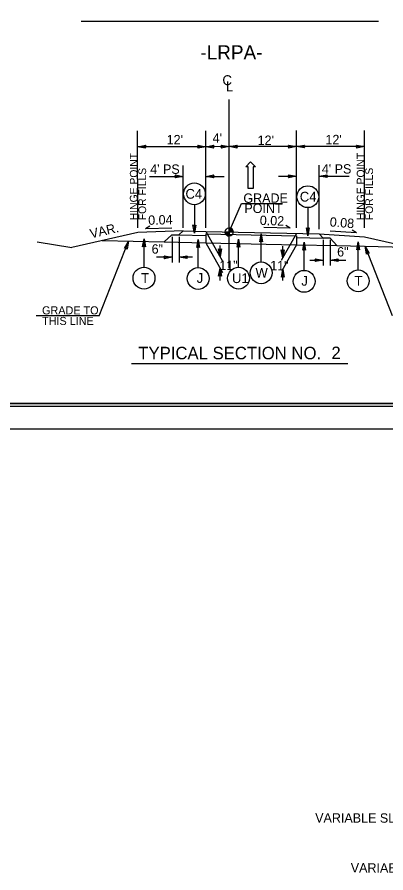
# Model space of a CAD drawing. Extents: x 2241081 to 2251104, y 658534 to 663427.
# Drawn here: x 2243527 to 2243852, y 661352 to 662106 of the extents above; entities that cross this region are included whole.
import ezdxf

# ---------------------------------------------------------------- set-up
doc = ezdxf.new("R2010")
doc.units = 0
for name, color, linetype in [('Old_Level_1', 7, 'Continuous'), ('Old_Level_11', 7, 'Continuous'), ('Old_Level_2', 7, 'Continuous'), ('Old_Level_3', 7, 'Continuous'), ('Prop Dimension Text', 7, 'Continuous'), ('Prop Lane Arrow CELL', 7, 'Continuous'), ('Prop PHM Text', 7, 'Continuous'), ('Sheet Cutting Line CELL', 7, 'Continuous'), ('Sheet Plan CELL', 7, 'Continuous'), ('Sheet Plot Border Inside CELL', 7, 'Continuous'), ('Sheet Plot Border Outside CELL', 7, 'Continuous'), ('Typical Arrow Superelevation CELL', 7, 'Continuous'), ('Typical Berm Information CELL', 7, 'Continuous'), ('Typical Grade Point Symbol CELL', 7, 'Continuous'), ('Typical Hinge Slope Interstate CELL', 7, 'Continuous'), ('Typical ID Circle CELL', 7, 'Continuous'), ('Typical Terminator CELL', 7, 'Continuous'), ('Typical Text Centerline CELL', 7, 'Continuous'), ('Typical Text Grade Point CELL', 7, 'Continuous'), ('Typical Text ID Circle CELL', 7, 'Continuous'), ('Typical Text Label CELL', 7, 'Continuous')]:
    doc.layers.add(name, color=color, linetype=linetype)

msp = doc.modelspace()

# ---------------------------------------------------------------- linework, layer by layer
at = {"layer": 'Old_Level_1'}
for p, q in [((2243633.23, 661915.97), (2243575.21, 661902.69)), ((2243833.22, 661912.13), (2243891.23, 661898.85))]:
    msp.add_line(p, q, dxfattribs=at)
at = {"layer": 'Old_Level_11'}
for p, q in [((2243599.25, 661842.46), (2243625.26, 661908.29)), ((2243857.83, 661842.43), (2243833.58, 661903.83))]:
    msp.add_line(p, q, dxfattribs=at)
at = {"layer": 'Old_Level_2'}
for p, q in [((2243673.22, 661917.27), (2243633.23, 661915.97)), ((2243673.22, 661917.27), (2243669.42, 661913.73)), ((2243673.22, 661917.27), (2243693.22, 661916.84)), ((2243693.22, 661916.84), (2243793.22, 661914.7)), ((2243693.22, 661914.73), (2243693.22, 661906.84)), ((2243693.22, 661914.73), (2243773.22, 661913.02)), ((2243793.22, 661914.7), (2243833.22, 661912.13)), ((2243793.22, 661914.7), (2243796.67, 661911.01)), ((2243544.72, 661907.78), (2243575.21, 661902.69)), ((2243601.87, 661908.79), (2243656.66, 661907.62)), ((2243663.31, 661913.81), (2243656.66, 661907.62)), ((2243656.66, 661907.62), (2243693.22, 661906.84)), ((2243663.31, 661913.81), (2243669.42, 661913.73)), ((2243669.42, 661913.73), (2243693.22, 661913.22)), ((2243773.23, 661913.02), (2243773.23, 661905.12)), ((2243773.23, 661911.51), (2243796.67, 661911.01)), ((2243802.78, 661910.92), (2243796.67, 661911.01)), ((2243802.78, 661910.92), (2243808.89, 661904.36)), ((2243693.22, 661906.84), (2243773.23, 661905.12)), ((2243773.23, 661905.12), (2243808.89, 661904.36)), ((2243808.89, 661904.36), (2243873.16, 661902.98))]:
    msp.add_line(p, q, dxfattribs=at)
at = {"layer": 'Prop Dimension Text'}
for p, q in [((2243633.22, 661919.92), (2243633.17, 662005.51)), ((2243693.22, 661919.96), (2243693.17, 662005.55)), ((2243773.22, 661920.01), (2243773.17, 662005.6)), ((2243833.22, 661920.04), (2243833.17, 662005.63)), ((2243693.18, 661991.48), (2243633.18, 661991.44)), ((2243713.86, 661991.49), (2243693.18, 661991.48)), ((2243753.18, 661991.52), (2243713.86, 661991.49)), ((2243773.18, 661991.53), (2243753.18, 661991.52)), ((2243833.18, 661991.56), (2243773.18, 661991.53)), ((2243673.22, 661919.95), (2243673.19, 661975.03)), ((2243793.22, 661918.71), (2243793.19, 661975.1)), ((2243643.74, 661965.32), (2243673.19, 661965.34)), ((2243693.19, 661965.35), (2243709.57, 661965.36)), ((2243757.46, 661965.39), (2243773.19, 661965.4)), ((2243793.19, 661965.41), (2243819.53, 661965.43)), ((2243693.22, 661916.84), (2243707.98, 661890.66)), ((2243773.24, 661915.12), (2243759.71, 661891.13)), ((2243663.63, 661912.05), (2243663.63, 661889.44)), ((2243669.74, 661912.05), (2243669.74, 661889.44)), ((2243796.67, 661909.55), (2243796.67, 661886.94)), ((2243802.78, 661909.55), (2243802.78, 661886.94)), ((2243693.22, 661906.84), (2243707.97, 661880.66)), ((2243705.78, 661894.57), (2243705.77, 661904.37)), ((2243773.23, 661905.12), (2243760.25, 661882.09)), ((2243761.07, 661893.54), (2243761.07, 661903.93)), ((2243663.57, 661894.06), (2243649.7, 661894.05)), ((2243681.39, 661894.07), (2243669.74, 661894.06)), ((2243705.79, 661873.61), (2243705.79, 661884.56)), ((2243785.01, 661891.57), (2243796.67, 661891.56)), ((2243802.84, 661891.56), (2243816.71, 661891.55)), ((2243761.05, 661873.57), (2243761.06, 661883.53)), ((2243599.25, 661842.46), (2243543.76, 661842.43))]:
    msp.add_line(p, q, dxfattribs=at)
at = {"layer": 'Prop Lane Arrow CELL'}
for p, q in [((2243728.45, 661973.86), (2243732.72, 661978.21)), ((2243732.72, 661978.21), (2243737.14, 661973.87)), ((2243730.52, 661973.86), (2243728.45, 661973.86)), ((2243730.53, 661954.57), (2243730.52, 661973.86)), ((2243737.14, 661973.87), (2243735.07, 661973.87)), ((2243735.07, 661973.87), (2243735.08, 661954.57)), ((2243735.08, 661954.57), (2243730.53, 661954.57))]:
    msp.add_line(p, q, dxfattribs=at)
at = {"layer": 'Sheet Cutting Line CELL'}
msp.add_line((2242806.13, 661742.89), (2244489.63, 661742.89), dxfattribs=at)
at = {"layer": 'Sheet Plan CELL'}
for points in [[(2242972.61, 661765.4), (2242972.59, 662815.38), (2244272.58, 662815.42), (2244272.59, 662665.35), (2244472.63, 662665.34), (2244472.63, 661765.4)], [(2244472.65, 662815.4), (2242972.62, 662815.4), (2242972.61, 661765.4), (2244472.63, 661765.4)]]:
    msp.add_lwpolyline(points, close=True, dxfattribs=at)
at = {"layer": 'Sheet Plot Border Inside CELL'}
msp.add_lwpolyline([(2242819.13, 661762.89), (2244485.11, 661762.9), (2244485.13, 662817.89), (2242819.13, 662817.89)], close=True, dxfattribs=at)
at = {"layer": 'Sheet Plot Border Outside CELL'}
msp.add_lwpolyline([(2242806.13, 661742.89), (2244489.63, 661742.89), (2244489.63, 662837.89), (2242806.13, 662837.89)], close=True, dxfattribs=at)
at = {"layer": 'Typical Arrow Superelevation CELL'}
for p, q in [((2243767.75, 661919.82), (2243763.83, 661922.19)), ((2243640.13, 661919.31), (2243644.02, 661921.71)), ((2243640.13, 661919.31), (2243663.42, 661920.01)), ((2243767.75, 661919.82), (2243744.45, 661920.29)), ((2243826.09, 661915.49), (2243802.83, 661916.95)), ((2243826.09, 661915.49), (2243822.28, 661918.02))]:
    msp.add_line(p, q, dxfattribs=at)
at = {"layer": 'Typical Grade Point Symbol CELL'}
for p, q in [((2243710.33, 661916.4), (2243713.91, 661916.4)), ((2243713.92, 661919.98), (2243713.91, 661916.4)), ((2243713.91, 661916.4), (2243713.92, 661919.98)), ((2243713.91, 661916.4), (2243713.91, 661912.82)), ((2243717.49, 661916.4), (2243713.91, 661916.4))]:
    msp.add_line(p, q, dxfattribs=at)
for points in [[(2243710.37, 661915.89), (2243710.37, 661916.4)], [(2243710.44, 661915.52), (2243710.44, 661916.4)], [(2243710.51, 661915.27), (2243710.51, 661916.4)], [(2243710.58, 661915.08), (2243710.58, 661916.4)], [(2243710.66, 661914.91), (2243710.66, 661916.4)], [(2243710.73, 661914.76), (2243710.73, 661916.4)], [(2243710.8, 661914.63), (2243710.8, 661916.4)], [(2243710.87, 661914.51), (2243710.87, 661916.4)], [(2243710.94, 661914.4), (2243710.94, 661916.4)], [(2243711.01, 661914.3), (2243711.01, 661916.4)], [(2243711.08, 661914.2), (2243711.08, 661916.4)], [(2243711.16, 661914.11), (2243711.16, 661916.4)], [(2243711.23, 661914.03), (2243711.23, 661916.4)], [(2243711.3, 661913.95), (2243711.3, 661916.4)], [(2243711.37, 661913.87), (2243711.37, 661916.4)], [(2243711.44, 661913.8), (2243711.44, 661916.4)], [(2243711.51, 661913.74), (2243711.51, 661916.4)], [(2243711.59, 661913.67), (2243711.59, 661916.4)], [(2243711.66, 661913.61), (2243711.66, 661916.4)], [(2243711.73, 661913.56), (2243711.73, 661916.4)], [(2243711.8, 661913.51), (2243711.8, 661916.4)], [(2243711.87, 661913.45), (2243711.87, 661916.4)], [(2243711.94, 661913.4), (2243711.94, 661916.4)], [(2243712.02, 661913.36), (2243712.02, 661916.4)], [(2243712.09, 661913.32), (2243712.09, 661916.4)], [(2243712.16, 661913.28), (2243712.16, 661916.4)], [(2243712.23, 661913.24), (2243712.23, 661916.4)], [(2243712.3, 661913.2), (2243712.3, 661916.4)], [(2243712.37, 661913.17), (2243712.37, 661916.4)], [(2243712.45, 661913.13), (2243712.45, 661916.4)], [(2243712.52, 661913.1), (2243712.52, 661916.4)], [(2243712.59, 661913.07), (2243712.59, 661916.4)], [(2243712.66, 661913.04), (2243712.66, 661916.4)], [(2243712.73, 661913.01), (2243712.73, 661916.4)], [(2243712.8, 661912.99), (2243712.8, 661916.4)], [(2243712.88, 661912.97), (2243712.88, 661916.4)], [(2243712.95, 661912.95), (2243712.95, 661916.4)], [(2243713.02, 661912.93), (2243713.02, 661916.4)], [(2243713.09, 661912.91), (2243713.09, 661916.4)], [(2243713.16, 661912.9), (2243713.16, 661916.4)], [(2243713.23, 661912.88), (2243713.23, 661916.4)], [(2243713.3, 661912.86), (2243713.3, 661916.4)], [(2243713.38, 661912.86), (2243713.38, 661916.4)], [(2243713.45, 661912.85), (2243713.45, 661916.4)], [(2243713.52, 661912.84), (2243713.52, 661916.4)], [(2243713.59, 661912.83), (2243713.59, 661916.4)], [(2243713.66, 661912.82), (2243713.66, 661916.4)], [(2243713.73, 661912.82), (2243713.73, 661916.4)], [(2243713.81, 661912.82), (2243713.81, 661916.4)], [(2243713.88, 661912.82), (2243713.88, 661912.82), (2243713.88, 661916.4)], [(2243713.96, 661916.4), (2243713.96, 661919.98), (2243713.96, 661919.98)], [(2243714.04, 661916.4), (2243714.04, 661919.98)], [(2243714.11, 661916.4), (2243714.11, 661919.97)], [(2243714.18, 661916.4), (2243714.18, 661919.97)], [(2243714.25, 661916.4), (2243714.25, 661919.96)], [(2243714.32, 661916.4), (2243714.32, 661919.95)], [(2243714.39, 661916.4), (2243714.39, 661919.94)], [(2243714.47, 661916.4), (2243714.47, 661919.93)], [(2243714.54, 661916.4), (2243714.54, 661919.92)], [(2243714.61, 661916.4), (2243714.61, 661919.91)], [(2243714.68, 661916.4), (2243714.68, 661919.89)], [(2243714.75, 661916.4), (2243714.75, 661919.87)], [(2243714.82, 661916.4), (2243714.82, 661919.86)], [(2243714.9, 661916.4), (2243714.9, 661919.83)], [(2243714.97, 661916.4), (2243714.97, 661919.82)], [(2243715.04, 661916.4), (2243715.04, 661919.79)], [(2243715.11, 661916.4), (2243715.11, 661919.77)], [(2243715.18, 661916.4), (2243715.18, 661919.75)], [(2243715.25, 661916.4), (2243715.25, 661919.71)], [(2243715.33, 661916.4), (2243715.33, 661919.68)], [(2243715.4, 661916.4), (2243715.4, 661919.65)], [(2243715.47, 661916.4), (2243715.47, 661919.62)], [(2243715.54, 661916.4), (2243715.54, 661919.59)], [(2243715.61, 661916.4), (2243715.61, 661919.55)], [(2243715.68, 661916.4), (2243715.68, 661919.51)], [(2243715.76, 661916.4), (2243715.76, 661919.47)], [(2243715.83, 661916.4), (2243715.83, 661919.42)], [(2243715.9, 661916.4), (2243715.9, 661919.37)], [(2243715.97, 661916.4), (2243715.97, 661919.32)], [(2243716.04, 661916.4), (2243716.04, 661919.28)], [(2243716.11, 661916.4), (2243716.11, 661919.22)], [(2243716.19, 661916.4), (2243716.19, 661919.17)], [(2243716.26, 661916.4), (2243716.26, 661919.1)], [(2243716.33, 661916.4), (2243716.33, 661919.04)], [(2243716.4, 661916.4), (2243716.4, 661918.97)], [(2243716.47, 661916.4), (2243716.47, 661918.9)], [(2243716.54, 661916.4), (2243716.54, 661918.82)], [(2243716.61, 661916.4), (2243716.61, 661918.74)], [(2243716.69, 661916.4), (2243716.69, 661918.66)], [(2243716.76, 661916.4), (2243716.76, 661918.57)], [(2243716.83, 661916.4), (2243716.83, 661918.47)], [(2243716.9, 661916.4), (2243716.9, 661918.37)], [(2243716.97, 661916.4), (2243716.97, 661918.26)], [(2243717.04, 661916.4), (2243717.04, 661918.13)], [(2243717.12, 661916.4), (2243717.12, 661918)], [(2243717.19, 661916.4), (2243717.19, 661917.84)], [(2243717.26, 661916.4), (2243717.26, 661917.68)], [(2243717.33, 661916.4), (2243717.33, 661917.46)], [(2243717.4, 661916.4), (2243717.4, 661917.21)], [(2243717.47, 661916.4), (2243717.47, 661916.79)]]:
    msp.add_lwpolyline(points, dxfattribs=at)
msp.add_circle((2243713.91, 661916.4), 3.58, dxfattribs=at)
for start, end in [(179.99048, 269.99048), (359.99048, 89.99048)]:
    msp.add_arc((2243713.91, 661916.4), 3.58, start, end, dxfattribs=at)
at = {"layer": 'Typical ID Circle CELL'}
for p, q in [((2243683.2, 661940.29), (2243683.2, 661915.44)), ((2243783.21, 661937.79), (2243783.21, 661912.94)), ((2243742.04, 661890), (2243742.04, 661914.85)), ((2243638.8, 661885.38), (2243638.8, 661910.23)), ((2243686.44, 661885.01), (2243686.44, 661909.79)), ((2243722.12, 661885.23), (2243722.12, 661910.08)), ((2243779.97, 661882.51), (2243779.97, 661907.28)), ((2243827.6, 661882.87), (2243827.6, 661907.73))]:
    msp.add_line(p, q, dxfattribs=at)
for centre in [(2243683.2, 661949.91), (2243783.21, 661947.41), (2243638.8, 661875.76), (2243686.48, 661875.4), (2243722.12, 661875.61), (2243742.04, 661880.38), (2243779.92, 661872.89), (2243827.6, 661873.26)]:
    msp.add_circle(centre, 9.62, dxfattribs=at)
at = {"layer": 'Typical Terminator CELL'}
for points in [[(2243640.21, 661990.24), (2243633.18, 661991.44), (2243640.25, 661992.7), (2243639.35, 661991.45)], [(2243686.15, 661992.69), (2243693.18, 661991.48), (2243686.11, 661990.23), (2243687.01, 661991.48)], [(2243700.21, 661990.27), (2243693.18, 661991.48), (2243700.25, 661992.73), (2243699.35, 661991.48)], [(2243706.83, 661992.7), (2243713.86, 661991.49), (2243706.8, 661990.24), (2243707.69, 661991.49)], [(2243720.89, 661990.29), (2243713.86, 661991.49), (2243720.93, 661992.75), (2243720.03, 661991.5)], [(2243766.15, 661992.73), (2243773.18, 661991.53), (2243766.11, 661990.27), (2243767.01, 661991.52)], [(2243780.21, 661990.32), (2243773.18, 661991.53), (2243780.25, 661992.78), (2243779.35, 661991.53)], [(2243826.15, 661992.77), (2243833.18, 661991.56), (2243826.11, 661990.31), (2243827.01, 661991.56)], [(2243666.16, 661966.54), (2243673.19, 661965.34), (2243666.12, 661964.08), (2243667.02, 661965.33)], [(2243700.22, 661964.14), (2243693.19, 661965.35), (2243700.26, 661966.6), (2243699.36, 661965.35)], [(2243766.16, 661966.6), (2243773.19, 661965.4), (2243766.12, 661964.14), (2243767.02, 661965.39)], [(2243800.22, 661964.2), (2243793.19, 661965.41), (2243800.26, 661966.66), (2243799.36, 661965.41)], [(2243684.41, 661922.47), (2243683.2, 661915.44), (2243681.95, 661922.51), (2243683.2, 661921.61)], [(2243740.82, 661907.82), (2243742.04, 661914.85), (2243743.29, 661907.78), (2243742.04, 661908.68)], [(2243784.42, 661919.97), (2243783.21, 661912.94), (2243781.96, 661920.01), (2243783.21, 661919.11)], [(2243621.55, 661902.2), (2243625.26, 661908.29), (2243623.83, 661901.26), (2243622.99, 661902.55)], [(2243637.59, 661903.2), (2243638.8, 661910.23), (2243640.05, 661903.16), (2243638.8, 661904.06)], [(2243685.23, 661902.76), (2243686.44, 661909.79), (2243687.69, 661902.72), (2243686.44, 661903.61)], [(2243720.91, 661903.05), (2243722.12, 661910.08), (2243723.37, 661903.01), (2243722.12, 661903.91)], [(2243778.76, 661900.25), (2243779.97, 661907.28), (2243781.22, 661900.21), (2243779.97, 661901.11)], [(2243826.39, 661900.7), (2243827.6, 661907.73), (2243828.85, 661900.66), (2243827.6, 661901.56)], [(2243706.98, 661901.6), (2243705.78, 661894.57), (2243704.52, 661901.63), (2243705.77, 661900.74)], [(2243762.28, 661900.56), (2243761.07, 661893.54), (2243759.82, 661900.61), (2243761.07, 661899.71)], [(2243835.03, 661896.85), (2243833.58, 661903.83), (2243837.34, 661897.72), (2243835.84, 661898.09)], [(2243656.54, 661895.27), (2243663.57, 661894.06), (2243656.5, 661892.81), (2243657.4, 661894.06)], [(2243676.77, 661892.86), (2243669.74, 661894.06), (2243676.81, 661895.32), (2243675.91, 661894.07)], [(2243789.64, 661892.78), (2243796.67, 661891.56), (2243789.6, 661890.31), (2243790.5, 661891.56)], [(2243809.87, 661890.34), (2243802.84, 661891.56), (2243809.91, 661892.8), (2243809.01, 661891.55)], [(2243704.58, 661877.53), (2243705.79, 661884.56), (2243707.04, 661877.49), (2243705.79, 661878.39)], [(2243759.84, 661876.5), (2243761.06, 661883.53), (2243762.3, 661876.46), (2243761.05, 661877.36)]]:
    msp.add_lwpolyline(points, close=True, dxfattribs=at)
at = {"layer": 'Typical Text Centerline CELL'}
msp.add_line((2243713.93, 661884.61), (2243713.84, 662033.16), dxfattribs=at)
at = {"layer": 'Typical Text Grade Point CELL'}
for p, q in [((2243713.91, 661916.4), (2243724.75, 661941.42)), ((2243724.75, 661941.42), (2243760.88, 661941.45))]:
    msp.add_line(p, q, dxfattribs=at)
at = {"layer": 'Typical Text Label CELL'}
for p, q in [((2243583.49, 662102.12), (2243845.46, 662102.12)), ((2243627.83, 661800.55), (2243818.32, 661800.55))]:
    msp.add_line(p, q, dxfattribs=at)

# ---------------------------------------------------------------- texts
at = {"layer": 'Old_Level_3'}
for s, p in [('GRADE TO', (2243548.93, 661843.78)), ('THIS LINE', (2243548.93, 661834.43))]:
    msp.add_text(s, height=7.131, rotation=359.99993, dxfattribs=at).set_placement(p)
at = {"layer": 'Prop Dimension Text'}
for s, height, rotation, p in [('-LRPA-', 12.5, 0.03489, (2243688.45, 662068.26)), ("12'", 8.25, 0.03489, (2243658.74, 661993.55)), ("4'", 8.25, 0.03489, (2243699.29, 661995.03)), ("12'", 8.25, 0.03489, (2243738.93, 661993.02)), ("12'", 8.25, 0.03489, (2243798.74, 661993.63)), ("4' PS", 8.25, 0.03489, (2243644.23, 661967.55)), ("4' PS", 8.25, 0.03489, (2243795.52, 661967.77)), ('VAR.', 8.25, 12.89031, (2243592.13, 661910.66)), ('6"', 8.25, 0.03489, (2243645.5, 661897.28)), ('6"', 8.25, 359.96498, (2243809.01, 661894.78)), ('11"', 8.25, 0.03489, (2243705.16, 661882.74)), ('11"', 8.25, 359.96498, (2243750.06, 661882.7))]:
    msp.add_text(s, height=height, rotation=rotation, dxfattribs=at).set_placement(p)
at = {"layer": 'Prop PHM Text'}
for s, height, p in [('HINGE POINT', 6.8193, (2243633.13, 661926.69)), ('HINGE POINT', 6.8193, (2243833.13, 661926.82)), ('FOR FILLS', 6.819, (2243640.64, 661926.69)), ('FOR FILLS', 6.819, (2243840.64, 661926.82))]:
    msp.add_text(s, height=height, rotation=89.99993, dxfattribs=at).set_placement(p)
at = {"layer": 'Typical Berm Information CELL'}
for s, rotation, p in [('0.04', 1.71348, (2243642.59, 661922.6)), ('0.02 ', 358.19158, (2243740.75, 661922.58)), ('0.08', 355.73792, (2243802.27, 661921.26))]:
    msp.add_text(s, height=8.25, rotation=rotation, dxfattribs=at).set_placement(p)
at = {"layer": 'Typical Hinge Slope Interstate CELL'}
for p in [(2243789.65, 661396.35), (2243821, 661352.34)]:
    msp.add_text('VARIABLE SLOPE', height=8.25, rotation=359.8157, dxfattribs=at).set_placement(p)
at = {"layer": 'Typical Text Centerline CELL'}
for s, rotation, p in [('C', 0.03489, (2243707.9, 662045.64)), ('L', 359.98179, (2243710.93, 662040.14))]:
    msp.add_text(s, height=8.76, rotation=rotation, dxfattribs=at).set_placement(p)
at = {"layer": 'Typical Text Grade Point CELL'}
for s, p in [('GRADE', (2243726.37, 661942.04)), ('POINT', (2243727.25, 661933.04))]:
    msp.add_text(s, height=8.25, rotation=0.03489, dxfattribs=at).set_placement(p)
at = {"layer": 'Typical Text ID Circle CELL'}
for s, height, p in [('C4', 8.608, (2243675.31, 661945.64)), ('C4', 8.608, (2243776.1, 661943.14)), ('W', 8.61, (2243737.05, 661876.15)), ('T', 8.61, (2243636.24, 661871.53)), ('J', 8.61, (2243685.26, 661871.55)), ('U1', 8.608, (2243716.35, 661871.38)), ('J', 8.61, (2243777.46, 661869.05)), ('T', 8.61, (2243824.35, 661869.02))]:
    msp.add_text(s, height=height, rotation=359.99993, dxfattribs=at).set_placement(p)
at = {"layer": 'Typical Text Label CELL'}
for s, height, p in [('TYPICAL SECTION NO.  ', 11.0106, (2243633.74, 661804.23)), ('2', 11.01, (2243803.96, 661804.38))]:
    msp.add_text(s, height=height, dxfattribs=at).set_placement(p)

doc.saveas('drawing.dxf')
